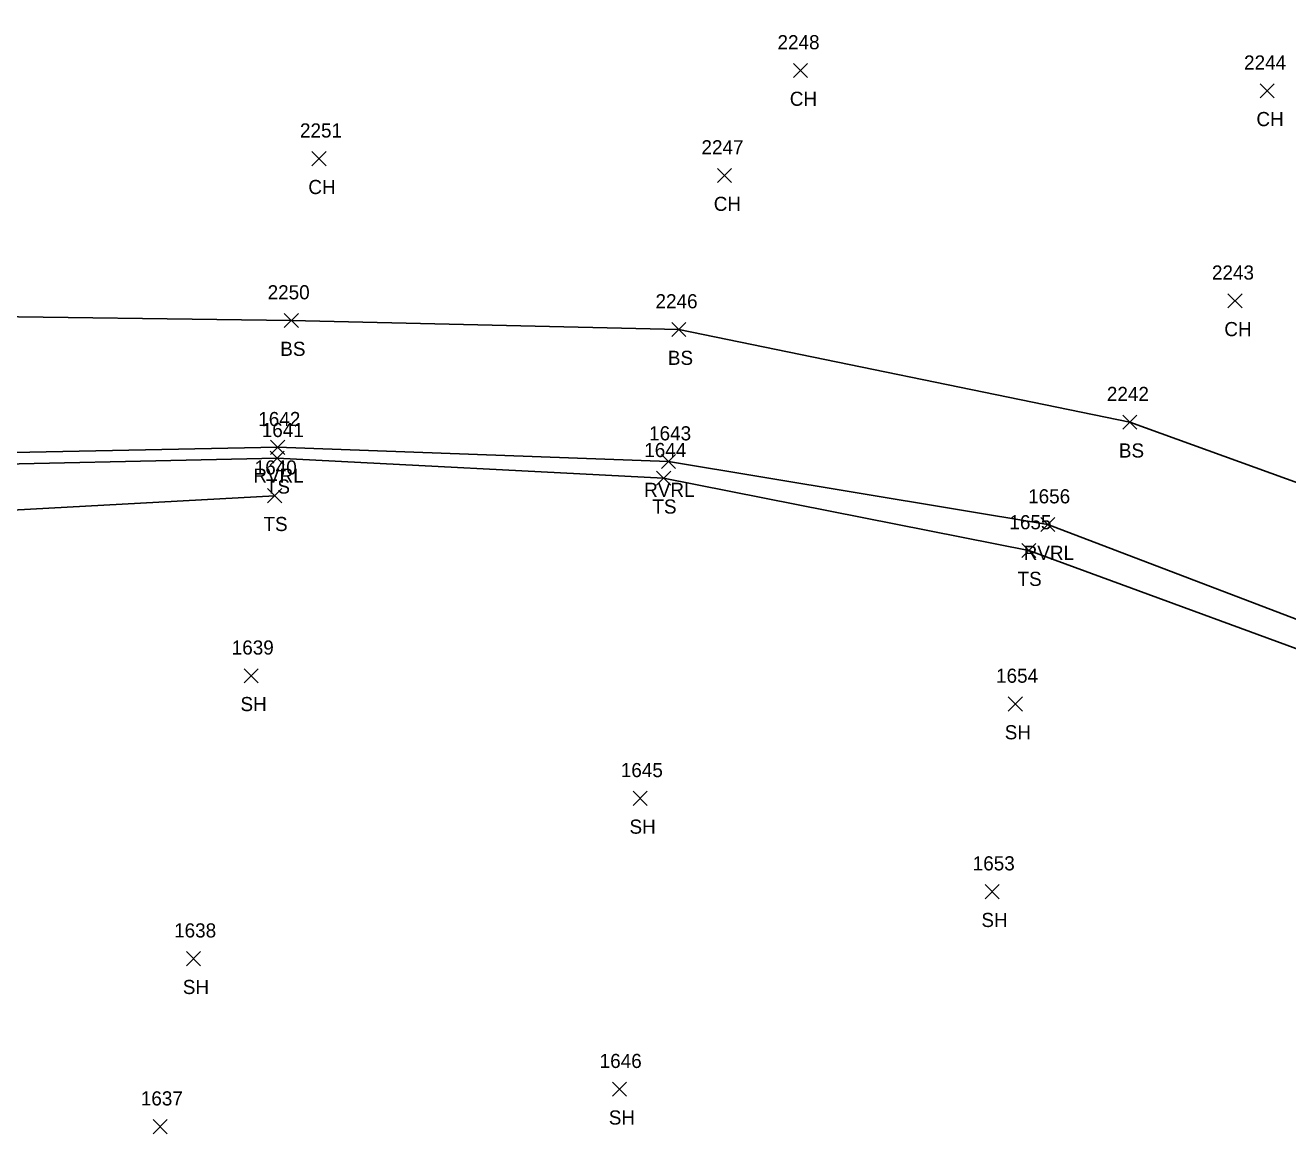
# Model space of a CAD drawing. Extents: x 1509053 to 1511576, y 400838 to 402572.
# Drawn here: x 1510102.6 to 1510281.3, y 401424.5 to 401581.3 of the extents above; entities that cross this region are included whole.
import ezdxf

# ---------------------------------------------------------------- set-up
doc = ezdxf.new("R2010")
doc.units = 0
for name, color, linetype in [('L_A', 7, 'Continuous'), ('L_I', 7, 'Continuous'), ('L_TIC', 7, 'Continuous'), ('LAWE', 7, 'Continuous'), ('LELB', 7, 'Continuous')]:
    doc.layers.add(name, color=color, linetype=linetype)

msp = doc.modelspace()

# ---------------------------------------------------------------- linework, layer by layer
at = {"layer": 'L_TIC'}
for points in [[(1510211.33, 401573.92), (1510213.33, 401575.92)], [(1510213.33, 401573.92), (1510211.33, 401575.92)], [(1510277.34, 401571.05), (1510279.34, 401573.05)], [(1510279.34, 401571.05), (1510277.34, 401573.05)], [(1510143.2, 401561.44), (1510145.2, 401563.44)], [(1510145.2, 401561.44), (1510143.2, 401563.44)], [(1510200.57, 401559.06), (1510202.57, 401561.06)], [(1510202.57, 401559.06), (1510200.57, 401561.06)], [(1510272.8, 401541.34), (1510274.8, 401543.34)], [(1510274.8, 401541.34), (1510272.8, 401543.34)], [(1510139.28, 401538.55), (1510141.28, 401540.55)], [(1510141.28, 401538.55), (1510139.28, 401540.55)], [(1510194.12, 401537.28), (1510196.12, 401539.28)], [(1510196.12, 401537.28), (1510194.12, 401539.28)], [(1510257.93, 401524.17), (1510259.93, 401526.17)], [(1510259.93, 401524.17), (1510257.93, 401526.17)], [(1510137.27, 401519.07), (1510139.27, 401521.07)], [(1510139.27, 401519.07), (1510137.27, 401521.07)], [(1510137.35, 401520.62), (1510139.35, 401522.62)], [(1510139.35, 401520.62), (1510137.35, 401522.62)], [(1510192.64, 401518.6), (1510194.64, 401520.6)], [(1510194.64, 401518.6), (1510192.64, 401520.6)], [(1510191.96, 401516.24), (1510193.96, 401518.24)], [(1510193.96, 401516.24), (1510191.96, 401518.24)], [(1510136.93, 401513.77), (1510138.93, 401515.77)], [(1510138.93, 401513.77), (1510136.93, 401515.77)], [(1510246.33, 401509.69), (1510248.33, 401511.69)], [(1510248.33, 401509.69), (1510246.33, 401511.69)], [(1510243.62, 401506.01), (1510245.62, 401508.01)], [(1510245.62, 401506.01), (1510243.62, 401508.01)], [(1510133.6, 401488.3), (1510135.6, 401490.3)], [(1510135.6, 401488.3), (1510133.6, 401490.3)], [(1510241.73, 401484.31), (1510243.73, 401486.31)], [(1510243.73, 401484.31), (1510241.73, 401486.31)], [(1510188.65, 401470.96), (1510190.65, 401472.96)], [(1510190.65, 401470.96), (1510188.65, 401472.96)], [(1510238.44, 401457.77), (1510240.43, 401459.77)], [(1510240.43, 401457.77), (1510238.44, 401459.77)], [(1510125.44, 401448.28), (1510127.44, 401450.28)], [(1510127.44, 401448.28), (1510125.44, 401450.28)], [(1510185.71, 401429.82), (1510187.71, 401431.82)], [(1510187.71, 401429.82), (1510185.71, 401431.82)], [(1510120.73, 401424.52), (1510122.73, 401426.52)], [(1510122.73, 401424.52), (1510120.73, 401426.52)]]:
    msp.add_lwpolyline(points, dxfattribs=at)
at = {"layer": 'LAWE'}
msp.add_lwpolyline([(1510025.36, 401521.25), (1510086.86, 401520.59), (1510138.35, 401521.62), (1510193.64, 401519.6), (1510247.33, 401510.69), (1510296.94, 401491.77), (1510361.96, 401428.29)], dxfattribs=at)
at = {"layer": 'LELB'}
for points in [[(1510375.28, 401447.94), (1510312.66, 401505.77), (1510258.93, 401525.17), (1510195.12, 401538.28), (1510140.28, 401539.55), (1510091.11, 401540.23), (1510018.72, 401547.48), (1509966.51, 401548.78), (1509913.37, 401571.2), (1509893.6, 401622.33), (1509860.64, 401660.7)], [(1510029.58, 401513.79), (1510086.69, 401518.94), (1510138.27, 401520.07), (1510192.96, 401517.24), (1510244.62, 401507.02), (1510296.57, 401487.98), (1510358.53, 401426.13)], [(1510086.94, 401511.99), (1510137.93, 401514.77)]]:
    msp.add_lwpolyline(points, dxfattribs=at)

# ---------------------------------------------------------------- texts
at = {"layer": 'L_A'}
for s, p in [('CH', (1510210.81, 401569.92)), ('CH', (1510276.83, 401567.05)), ('CH', (1510142.69, 401557.44)), ('CH', (1510200.05, 401555.06)), ('CH', (1510272.29, 401537.34)), ('BS', (1510138.72, 401534.55)), ('BS', (1510193.56, 401533.28)), ('BS', (1510257.37, 401520.17)), ('RVRL', (1510134.91, 401516.62)), ('TS', (1510136.68, 401515.07)), ('RVRL', (1510190.2, 401514.6)), ('TS', (1510191.37, 401512.24)), ('TS', (1510136.34, 401509.77)), ('RVRL', (1510243.9, 401505.69)), ('TS', (1510243.03, 401502.01)), ('SH', (1510133.09, 401484.3)), ('SH', (1510241.22, 401480.31)), ('SH', (1510188.13, 401466.96)), ('SH', (1510237.92, 401453.76)), ('SH', (1510124.93, 401444.28)), ('SH', (1510185.2, 401425.82))]:
    msp.add_text(s, height=2, dxfattribs=at).set_placement(p)
at = {"layer": 'L_I'}
for s, p in [('2248', (1510209.07, 401577.92)), ('2244', (1510275.08, 401575.05)), ('2251', (1510141.51, 401565.44)), ('2247', (1510198.31, 401563.06)), ('2243', (1510270.54, 401545.34)), ('2250', (1510136.93, 401542.55)), ('2246', (1510191.81, 401541.28)), ('2242', (1510255.67, 401528.17)), ('1642', (1510135.61, 401524.62)), ('1641', (1510136.1, 401523.07)), ('1643', (1510190.9, 401522.6)), ('1644', (1510190.22, 401520.24)), ('1640', (1510135.1, 401517.77)), ('1656', (1510244.53, 401513.69)), ('1655', (1510241.88, 401510.02)), ('1639', (1510131.85, 401492.3)), ('1654', (1510239.99, 401488.31)), ('1645', (1510186.9, 401474.96)), ('1653', (1510236.69, 401461.77)), ('1638', (1510123.7, 401452.28)), ('1646', (1510183.91, 401433.82)), ('1637', (1510118.99, 401428.52))]:
    msp.add_text(s, height=2, dxfattribs=at).set_placement(p)

doc.saveas('drawing.dxf')
